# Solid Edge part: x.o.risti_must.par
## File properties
Author: Romil
Template: iso part.par
Last saved by: Romil
Revision: 37
Application: Solid Edge
Accuracy: 0.990
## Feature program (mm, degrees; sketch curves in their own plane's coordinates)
sketch used by "unnamed Protrusion 1" plane through (0, 0, 0) normal (0, -1, 0) x-axis (1, 0, 0)
extrude "unnamed Protrusion 1" add finite 7.8 symmetric
sketch used by "ExtrudedProtrusion_4" plane through (0, 0, 0) normal (1, 0, 0) x-axis (0, 1, 0)
extrude "ExtrudedProtrusion_4" add finite 7.8 symmetric
sketch for "unnamed RevolvedCutout 1" plane through (0, 0, 0) normal (0, -1, 0) x-axis (1, 0, 0)
revolve "unnamed RevolvedCutout 1" cut finite 360 deg
sketch for "unnamed Protrusion 2" plane through (0, 0, 0) normal (0, 0, 1) x-axis (1, 0, 0)
  line (-3.6217, 3.6) -> (-2.7879, 3.6)
  line (-2.7879, 3.6) -> (-2.7879, -3.6)
  line (-2.7879, -3.6) -> (-3.6217, -3.6)
  line (-3.6217, -3.6) -> (-3.6217, 1.953)
  line (-3.6217, 3.6) -> (-3.6217, 1.953)
extrude "unnamed Protrusion 2" add to key point along +normal
mirror "unnamed Mirror 1" of "unnamed Protrusion 2" about plane through (0, 0, 0) normal (1, 0, 0)
extrude "unnamed Protrusion 3" add finite 7.9783
sketch for "unnamed Protrusion 4" plane through (0, 0, 0) normal (0, 0, 1) x-axis (1, 0, 0)
  line (3.35, -0.6) -> (-3.35, -0.6)
  line (-3.35, -0.6) -> (-3.35, 0.6)
  line (-3.35, 0.6) -> (3.35, 0.6)
  line (3.35, 0.6) -> (3.35, -0.6)
extrude "unnamed Protrusion 4" add to key point along +normal
sketch for "unnamed Cutout 1" plane through (0, -3.9, 7.9783) normal (0, -1, 0) x-axis (1, 0, 0)
extrude "unnamed Cutout 1" cut finite 0.9 along -normal
mirror "unnamed Mirror 2" of "unnamed Cutout 1" about plane through (0, 0, 0) normal (0, -1, 0)
extrude "unnamed Cutout 2" cut finite 0.9
sketch for "ExtrudedCutout_17" plane through (0, 0, 0) normal (0, -1, 0) x-axis (1, 0, 0)
extrude "ExtrudedCutout_17" cut finite 184.7238 symmetric
sketch for "ExtrudedCutout_21" plane through (0, 0, 0) normal (1, 0, 0) x-axis (0, 1, 0)
  arc centre (0, 0) radius 2.35 from (-2.181, -0.875) to (-2.181, 0.875) cw
  arc centre (0, 0) radius 2.35 from (-0.875, 2.181) to (0.875, 2.181) cw
  arc centre (0, 0) radius 2.35 from (2.181, 0.875) to (2.181, -0.875) cw
extrude "ExtrudedCutout_21" cut finite 60.1924 symmetric
fillet "Round_8" radius 0.2
sketch for "ExtrudedCutout_22" plane through (0, 0, 0) normal (0, -1, 0) x-axis (1, 0, 0)
  line (2.7, 0.6) -> (-2.7, 0.6)
  line (-2.7, 0.6) -> (-2.7, -0.6)
  line (-2.7, -0.6) -> (2.7, -0.6)
  line (2.7, -0.6) -> (2.7, 0.6)
extrude "ExtrudedCutout_22" cut finite 85.6625 symmetric
fillet "Round_9" radius 0.4
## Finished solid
Body 1: solid body, 81 faces, 198 edges, 116 vertices.
  Faces by surface: plane 36, cylinder 35, blend 8, torus 2
  Edges by curve: line 100, circle 58, intersection 24, ellipse 16
Bounding box of the edges (mm; curved faces can reach further): 7.800 x 7.800 x 15.200, from (-3.9, -3.9, -3.6) to (3.9, 3.9, 11.6).
Cylindrical faces by radius (mm): R0.1 x4, R0.2 x2, R0.4 x16, R2.35 x4, R2.4 x1, R3.0587 x3, R3.1 x2, R3.6 x2, R3.6217 x1
Toroidal faces (ring radius, tube radius in mm): R3.3 r0.3 x2
Planar faces by outward normal: +x 5, +y 7, +z 4, -x 5, -y 7, -z 8
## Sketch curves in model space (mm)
line (2.7, 0, -0.6) -> (2.7, 0, 0.6)
line (2.7, 0, 0.6) -> (-2.7, 0, 0.6)
line (-2.7, 0, 0.6) -> (-2.7, 0, -0.6)
line (-2.7, 0, -0.6) -> (2.7, 0, -0.6)
line (-3.35, -0.6, 0) -> (-3.35, 0.6, 0)
line (-3.35, 0.6, 0) -> (3.35, 0.6, 0)
line (3.35, 0.6, 0) -> (3.35, -0.6, 0)
line (3.35, -0.6, 0) -> (-3.35, -0.6, 0)
line (-4.4651, 0, 0) -> (5.0671, 0, 0)
line (2.7, 0, 3.0587) -> (2.7, 0, 3.3)
arc centre (3, 0, 3.3) radius 0.3 from (2.7, 0, 3.3) through (2.7941, 0, 3.5182) to (3, 0, 3.6)
line (3, 0, 3.6) -> (3.9, 0, 3.6)
line (3.9, 0, 3.6) -> (3.9, 0, 4.041)
line (3.9, 0, 4.041) -> (-3.9, 0, 4.041)
line (-3.9, 0, 4.041) -> (-3.9, 0, 3.6)
line (-3.9, 0, 3.6) -> (-3, 0, 3.6)
arc centre (-3, 0, 3.3) radius 0.3 from (-2.7, 0, 3.3) through (-2.7941, 0, 3.5182) to (-3, 0, 3.6)
line (-2.7, 0, 3.3) -> (-2.7, 0, 3.0587)
line (-2.7, 0, 3.0587) -> (2.7, 0, 3.0587)
circle centre (0, 0, 7.9783) radius 2.4
circle centre (0, 0, 7.9783) radius 3.6217
line (-3.6217, -3.6, 0) -> (-3.6217, 1.953, 0)
line (-2.7879, -3.6, 0) -> (-3.6217, -3.6, 0)
line (-2.7879, 3.6, 0) -> (-2.7879, -3.6, 0)
line (-3.6217, 3.6, 0) -> (-2.7879, 3.6, 0)
line (-3.6217, 3.6, 0) -> (-3.6217, 1.953, 0)
circle centre (0, -3.9, 7.9783) radius 3.1
circle centre (0, 0, 0) radius 3.6
circle centre (0, 0, 8) radius 3.6
arc centre (0, -0.975, -0.975) radius 0.1 from (0, -0.975, -0.875) through (0, -0.9023, -0.9064) to (0, -0.875, -0.975)
line (0, -0.875, -0.975) -> (0, -0.875, -2.181)
arc centre (0, 0, 0) radius 2.35 from (0, 0.875, -2.181) through (0, 0, -2.35) to (0, -0.875, -2.181)
line (0, 0.875, -2.181) -> (0, 0.875, -0.975)
arc centre (0, 0.975, -0.975) radius 0.1 from (0, 0.875, -0.975) through (0, 0.9064, -0.9023) to (0, 0.975, -0.875)
line (0, 0.975, -0.875) -> (0, 2.181, -0.875)
arc centre (0, 0, 0) radius 2.35 from (0, 2.181, 0.875) through (0, 2.35, 0) to (0, 2.181, -0.875)
line (0, 2.181, 0.875) -> (0, 0.975, 0.875)
arc centre (0, 0.975, 0.975) radius 0.1 from (0, 0.975, 0.875) through (0, 0.9023, 0.9064) to (0, 0.875, 0.975)
line (0, 0.875, 0.975) -> (0, 0.875, 2.181)
arc centre (0, 0, 0) radius 2.35 from (0, -0.875, 2.181) through (0, 0, 2.35) to (0, 0.875, 2.181)
line (0, -0.875, 2.181) -> (0, -0.875, 0.975)
arc centre (0, -0.975, 0.975) radius 0.1 from (0, -0.875, 0.975) through (0, -0.9064, 0.9023) to (0, -0.975, 0.875)
line (0, -0.975, 0.875) -> (0, -2.181, 0.875)
arc centre (0, 0, 0) radius 2.35 from (0, -2.181, -0.875) through (0, -2.35, 0) to (0, -2.181, 0.875)
line (0, -2.181, -0.875) -> (0, -0.975, -0.875)
line (0, 3.6, 0) -> (0, 3.9, 11.6)
arc centre (0, 0, 0) radius 3.6 from (0, 3.6, 0) through (0, -0.1067, -3.5984) to (0, -3.6, 0)
line (0, -3.6, 0) -> (0, -3.9, 11.6)
line (0, 0, 11.6) -> (0, -3.9, 11.6)
line (0, 0, 11.6) -> (0, 3.9, 11.6)
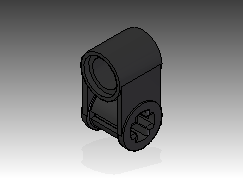
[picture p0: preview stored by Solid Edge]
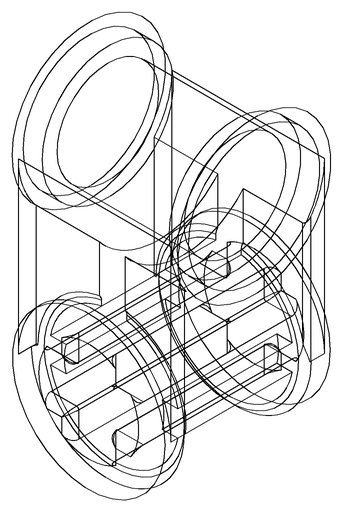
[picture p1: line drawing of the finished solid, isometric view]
